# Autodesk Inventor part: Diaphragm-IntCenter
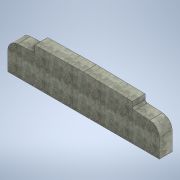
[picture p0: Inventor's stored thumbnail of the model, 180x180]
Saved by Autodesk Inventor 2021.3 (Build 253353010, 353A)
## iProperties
Created: 2021-10
Part Number: Diaphragm-IntCenter
Material: Concrete, Precast
Document SubType Name: Modeling
Designer: u1426
Density: 2.40731 g/cm^3
Appearance: Smooth Precast Structural
Author: u1426
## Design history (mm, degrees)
sketch "Sketch1"
  geometry: L1 (-762, 1295.4)-(-762, 1261.45); L2 (-726.164, 1223.417)-(-419.726, 1205.177); L3 (-228.6, 1002.336)-(-228.6, 635); L4 (-3225.8, 635)-(-3225.8, 1002.336); L5 (-2692.4, 1261.45)-(-2692.4, 1295.4); L6 (-2728.236, 1223.417)-(-3034.674, 1205.177); L7 (-3225.8, 635)-(-228.6, 635); L8 (-3302, 1295.4)-(-3302, 152.4); L9 (-152.4, 1295.4)-(-152.4, 152.4); L10 (-2692.4, 1295.4)-(-3302, 1295.4); L11 (-762, 1295.4)-(-152.4, 1295.4); L12 (-3302, 152.4)-(-4872.129, 152.4); L13 (-152.4, 152.4)-(-1248.139, 152.4); L14 (-2692.4, 1295.4)-(-2692.4, 1357.884); L15 (-762, 1357.884)-(-762, 1295.4); L16 (-2692.4, 1357.884)-(-1727.2, 1377.188); L17 (-1727.2, 1377.188)-(-762, 1357.884); A1 r 203.2 centre (-431.8, 1002.336) between (-228.6, 1002.336) and (-419.726, 1205.177); A2 r 38.1 centre (-723.9, 1261.45) between (-762, 1261.45) and (-726.164, 1223.417); A3 r 203.2 centre (-3022.6, 1002.336) between (-3034.674, 1205.177) and (-3225.8, 1002.336); A4 r 38.1 centre (-2730.5, 1261.45) between (-2728.236, 1223.417) and (-2692.4, 1261.45); 5 further points
  constraints: 34 end point, 8 point on circle, 8 point on line, 8 tangent, 5 vertical, 4 centre point, 2 horizontal, 2 perpendicular, 1 parallel
  dimensions: "d12" = 69.85 distance of L1.start point (-762, 1225.55); "d16" = 31.75 vertical distance of point (-762, 1225.55) point (-228.6, 1193.8); "d23" = 203.2 radius of A1; "d24" = 38.1 radius of A2; "d68" = 533.4 horizontal distance of point (-2692.4, 1225.55) point (-3225.8, 1193.8); "d69" = 31.75 vertical distance of point (-2692.4, 1225.55) point (-3225.8, 1193.8); "d70" = 69.85 distance of point (-2692.4, 1225.55) L5.end; "d78" = 203.2 radius of A3; "d79" = 38.1 radius of A4; "d82" = 76.2 distance between parallel lines of L3 L9; "d83" = 76.2 distance between parallel lines of L4 L8; "d84" = 1143 distance of L9.start L9.end; "d85" = 1143 distance of L8.start L8.end (= d84); "d86" = 482.6 distance from line of L4.start L12 (= d87); "d87" = 482.6 distance from line of L3.end L13; "d88" = 0 distance between parallel lines of L13 L12; "d89" = 3149.6 distance between parallel lines of L9 L8; "d90" = 62.484 distance of L5.end L14.end; "d91" = 152.4 distance from line of point (0, 0) L13; "d92" = 152.4 distance from line of point (0, 0) L9; "d93" = 533.4 distance between parallel lines of L3 L1; "d96" = 965.2 horizontal distance of L14.end L16.end; "d97" = 965.2 horizontal distance of L16.end L15.start (derived); "d98" = 19.304 vertical distance of L14.end L16.end (= 0.02 x d96); "d99" = 19.304 vertical distance of L16.end L15.start (= 0.02 x d97); "d100" = 62.484 distance of L15.start L1.start (derived)
extrude "Extrusion9" new body sketch "Sketch1" stored distance "d94" = 254; taper "d95" = 0 deg
body "Solid4"
